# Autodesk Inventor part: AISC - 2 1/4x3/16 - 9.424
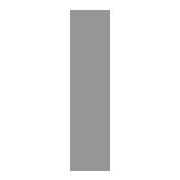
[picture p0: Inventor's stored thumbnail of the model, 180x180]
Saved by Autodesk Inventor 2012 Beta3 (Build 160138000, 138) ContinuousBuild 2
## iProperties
_CCFamilyMember: 147
_CCFamilyDisplayName: ANSI AISC (Rectangular) - Flat Bar Steel
_FrameMemberDoc: Frame Member File
_Version: 15.0.0
_GetPNFromCC: 1
Created: 2010-11
Part Number: AISC - 2 1/4x3/16 - 9.424
Material: Steel, Mild
Description: Flat Bar Steel
Document SubType Name: Modeling
Standard: ANSI
Designer: Beta-8540w
Standards Organization: ANSI
Language: en-US
Size Designation: 2 1/4x3/16
Categories: <MemberInstance><Categories><Category DisplayName="Structural Shapes" InternalName="089c4875-fa83-4c05-b084-43b9cc11f5ed" Mnemonic="GRDR"><CategoryParameter Dis
Stock Number: 2 1/4x3/16
Density: 7.86 g/cm^3
IsCustomPart: 1
G_L: 9.424 in
G_W: 0.188 in
G_H: 2.250 in
Author: Beta-8540w
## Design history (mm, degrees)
node "Start plane"
node "End plane"
node "Driven Length"
  sketch "Sketch3"
    geometry: L1 (0, 0)-(10, 0) reference
    constraints: 2 end point, 1 horizontal
  workplane "Work Plane3"
  sketch "Sketch4"
    geometry: L1 (-2, 0)-(12, 0) reference; L2 (-40.005, 239.358)-(40.005, 239.358) reference
    dimensions: "d9" = 239.35777 distance between parallel lines of L1 L2 (derived)
sketch "Sweep Path"
  geometry: L1 through (25.4, 40.279) direction (1, 0); L2 through (112.121, 127) direction (1, 0); 8 other entities
  constraints: 10 horizontal
node "Orientation Work Plane"
feature "Body" dims "d10" = 0
body "Solid1"
sketch "Sketch"
  geometry: L1 (2.381, -28.575)-(-2.381, -28.575); L2 (-2.381, -28.575)-(-2.381, 28.575); L3 (-2.381, 28.575)-(2.381, 28.575); L4 (2.381, 28.575)-(2.381, -28.575); L5 (-6, 0)-(8, 0); L6 (0, -30)-(0, 40); L7 (0, 54)-(0, -44); L8 (-9.2, 0)-(13.2, 0)
  constraints: 16 end point, 2 collinear, 2 parallel, 1 horizontal, 1 perpendicular
  dimensions: "d0" = 57.15 distance between parallel lines of L3 L1 (= G_W); "d1" = 4.7625 distance between parallel lines of L4 L2 (= G_H); "d4" = 2.38125 distance between parallel lines of L6 L4 (= 0.5 x d1); "d5" = 28.575 distance between parallel lines of L5 L3 (= 0.5 x d0)
other parameters: "G_W" = 57.15 [user parameter; used in 1 equation term], "G_H" = 4.7625 [user parameter; used in 1 equation term], "G_L" = 239.35777 (= d9) [user parameter], "G_OFFSET_START" = 0 [user parameter; used in 1 equation term], "G_OFFSET_END" = 0 [user parameter; used in 1 equation term], "d6" = 0 (computed from G_OFFSET_START), "d7" = 239.35777 (= G_OFFSET_END + B_L), "B_L" = 239.35777 [user parameter; used in 1 equation term], "d8" = 90 deg
